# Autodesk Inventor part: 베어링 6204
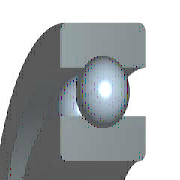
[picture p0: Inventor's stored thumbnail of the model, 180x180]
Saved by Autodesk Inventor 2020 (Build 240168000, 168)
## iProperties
Created: 2012-02
Part Number: 베어링 6204
Material: 강철, 연강
Description: 깊은 그루브 볼 베어링
Document SubType Name: Modeling
Standard: KS B 2023
Designer: mduedu
Standards Organization: KS
Language: ko-KR
Size Designation: 6203 - 17 x 40 x 12
Categories: <MemberInstance><Categories><Category DisplayName="샤프트 부품" InternalName="7f7aeb1f-a693-4053-b835-cee3144e0d98" Mnemonic="SHFT"><Category DisplayName="베어링" Inter
Density: 1 g/cm^3
Appearance: 노란색
IsCustomPart: 1
Author: mduedu
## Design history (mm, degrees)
sketch "스케치" dims "d0" = 7.02 (= -0.26 x WD + 0.26 x BD)
  geometry: L1 (3.49, 16.75)-(10.51, 16.75); L2 (7, 16.75)-(7, 13.24); L3 (7, 16.75)-(7, 20.26); L4 (4.392, 14.401)-(0, 14.401); L5 (0, 10)-(14, 10); L6 (4.392, 19.099)-(0, 19.099); L7 (0, 23.5)-(14, 23.5); L8 (14, 10)-(14, 14.401); L9 (9.608, 14.401)-(14, 14.401); L10 (9.608, 19.099)-(14, 19.099); L11 (14, 23.5)-(14, 19.099); L12 (-2.4, 0)-(14.4, 0) reference; L13 (0, 7.3)-(0, 26.2) reference
  constraints: 22 end point, 4 point on line, 2 collinear, 2 perpendicular, 2 symmetric about line, 1 midpoint, 1 parallel, 14 other
  dimensions: "d9" = 20 diameter of L5 L12 (= WD); "d11" = 47 diameter of L7 L12 (= BD); "d12" = 14 distance between parallel lines of L8 L13 (= KB); "d13" = 28.802 diameter of L9 L12 (= 0.326 x BD + 0.674 x WD)
revolve "본체" stored, may be unused: angle "d6" = 90 deg
revolve "볼" stored, may be unused: angle "d7" = 90 deg
pattern_circular "IDS_ARRAYBALL[SIMPL:T]" dims angle "d3" = 360 deg
body "Solid1"
fillet "모깎기1" dims "d1" = 1 (= KRS)
other parameters: "WD" = 20 [user parameter; used in 5 equation terms], "BD" = 47 [user parameter; used in 5 equation terms], "KB" = 14 [user parameter; used in 1 equation term], "KRS" = 1 [user parameter; used in 1 equation term], "d4" = 0, "d5" = 0, "d8" = 0, "d14" = 0, "d15" = 0, "BBA" = 0 [user parameter], "BC0" = 4750000 [user parameter], "BC" = 9560000 [user parameter], "BR" = 23.5 (= 0.5 x BD) [user parameter]
